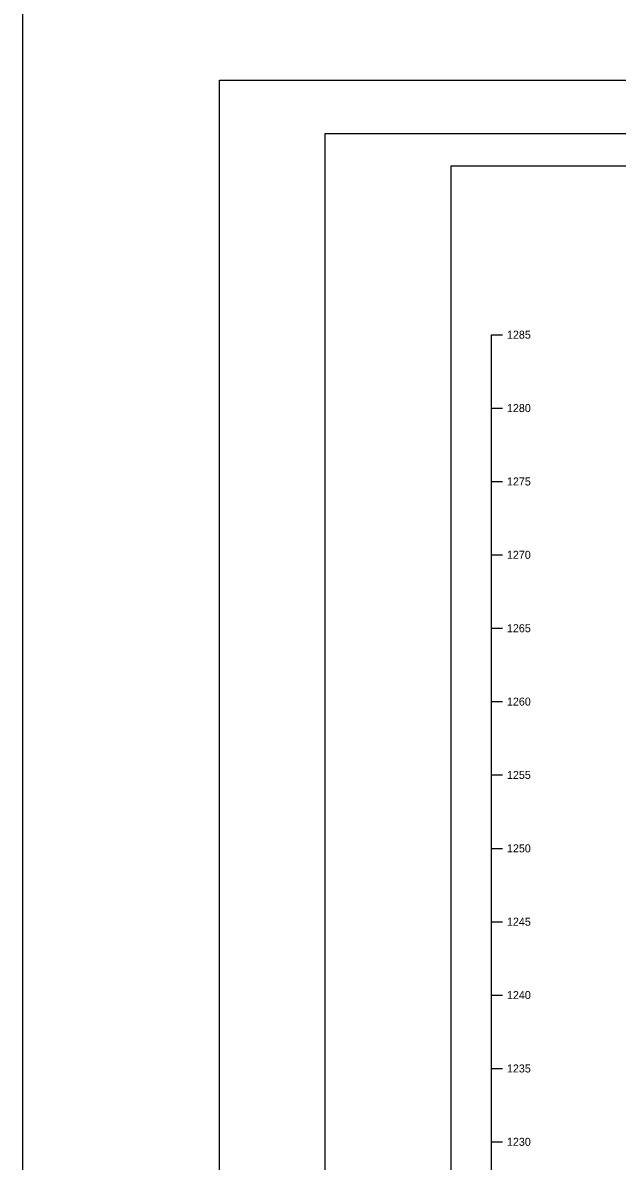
# Model space of a CAD drawing. Extents: x 2150161.5 to 2150203.1, y 143779.5 to 143868.5.
# Drawn here: x 2150161.53 to 2150170.73, y 143816.95 to 143834.58 of the extents above; entities that cross this region are included whole.
import ezdxf

# ---------------------------------------------------------------- set-up
doc = ezdxf.new("R2010")
doc.units = 0
for name, color, linetype in [('Default', 7, 'Continuous'), ('S', 7, 'Continuous'), ('SHT_Plot_Shape_Full', 7, 'Continuous'), ('SHT_Plot_Shape_Half', 7, 'Continuous'), ('SHT_Sheet_Border', 7, 'Continuous')]:
    doc.layers.add(name, color=color, linetype=linetype)

msp = doc.modelspace()

# ---------------------------------------------------------------- linework, layer by layer
at = {"layer": 'Default'}
msp.add_line((2150168.788, 143816.11), (2150168.788, 143829.746), dxfattribs=at)
for points in [[(2150168.788, 143829.746), (2150168.955, 143829.746)], [(2150168.788, 143828.61), (2150168.955, 143828.61)], [(2150168.788, 143827.473), (2150168.955, 143827.473)], [(2150168.788, 143826.337), (2150168.955, 143826.337)], [(2150168.788, 143825.2), (2150168.955, 143825.2)], [(2150168.788, 143824.064), (2150168.955, 143824.064)], [(2150168.788, 143822.928), (2150168.955, 143822.928)], [(2150168.788, 143821.791), (2150168.955, 143821.791)], [(2150168.788, 143820.655), (2150168.955, 143820.655)], [(2150168.788, 143819.519), (2150168.955, 143819.519)], [(2150168.788, 143818.382), (2150168.955, 143818.382)], [(2150168.788, 143817.246), (2150168.955, 143817.246)]]:
    msp.add_lwpolyline(points, dxfattribs=at)
at = {"layer": 'S'}
msp.add_lwpolyline([(2150161.53, 143868.477), (2150203.071, 143868.477), (2150203.071, 143779.536), (2150161.53, 143779.536)], close=True, dxfattribs=at)
at = {"layer": 'SHT_Plot_Shape_Full'}
msp.add_lwpolyline([(2150164.575, 143833.688), (2150200.575, 143833.688), (2150200.575, 143809.688), (2150164.575, 143809.688)], close=True, dxfattribs=at)
at = {"layer": 'SHT_Plot_Shape_Half'}
msp.add_lwpolyline([(2150166.212, 143832.863), (2150200.212, 143832.863), (2150200.212, 143810.863), (2150166.212, 143810.863)], close=True, dxfattribs=at)
at = {"layer": 'SHT_Sheet_Border'}
msp.add_lwpolyline([(2150199.662, 143811.363), (2150168.162, 143811.363), (2150168.162, 143832.363), (2150199.662, 143832.363)], close=True, dxfattribs=at)

# ---------------------------------------------------------------- texts
at = {"layer": 'Default'}
for s, p in [('1285', (2150169.025, 143829.684)), ('1280', (2150169.025, 143828.548)), ('1275', (2150169.025, 143827.411)), ('1270', (2150169.025, 143826.275)), ('1265', (2150169.025, 143825.138)), ('1260', (2150169.025, 143824.002)), ('1255', (2150169.025, 143822.866)), ('1250', (2150169.025, 143821.729)), ('1245', (2150169.025, 143820.593)), ('1240', (2150169.025, 143819.457)), ('1235', (2150169.025, 143818.32)), ('1230', (2150169.025, 143817.184))]:
    msp.add_text(s, height=0.124, dxfattribs=at).set_placement(p)

doc.saveas('drawing.dxf')
